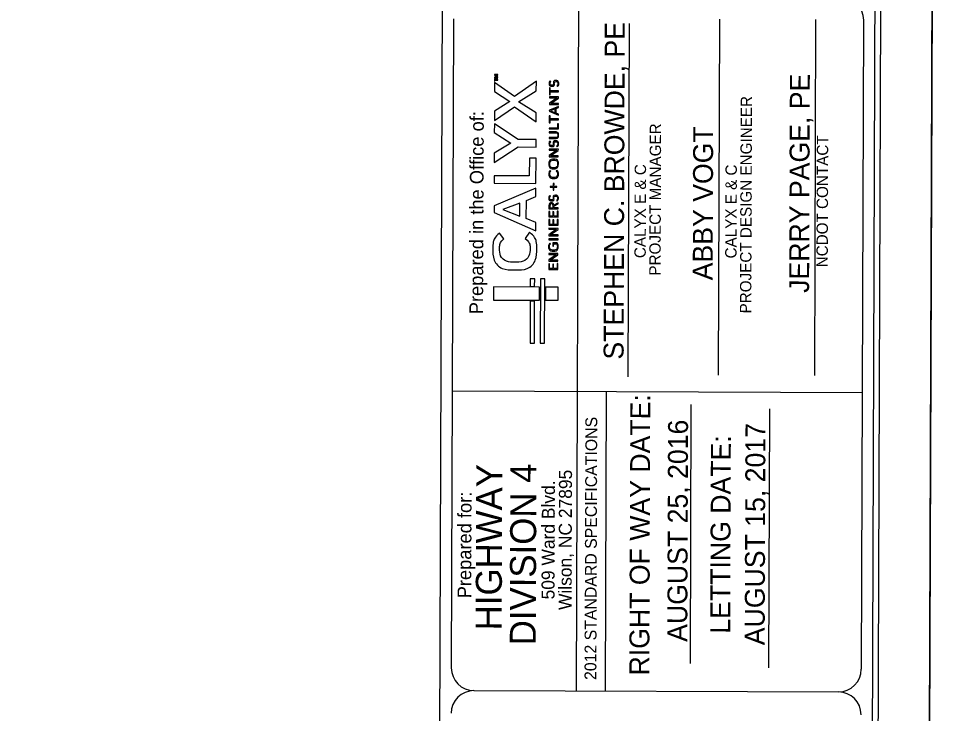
# Model space of a CAD drawing. Extents: x 2364794 to 2387902, y 795230 to 810426.
# Drawn here: x 2369718 to 2372593, y 805280 to 807415 of the extents above; entities that cross this region are included whole.
import ezdxf

# ---------------------------------------------------------------- set-up
doc = ezdxf.new("R2010")
doc.units = 0
for name, color, linetype in [('Mis Object Lines', 7, 'Continuous'), ('Old_Level_21', 7, 'Continuous'), ('Old_Level_22', 7, 'Continuous'), ('Old_Level_3', 7, 'Continuous'), ('Plan Sheet CELL', 7, 'Continuous'), ('Sub End Bent Cap Lines CELL', 7, 'Continuous')]:
    doc.layers.add(name, color=color, linetype=linetype)

msp = doc.modelspace()

# ---------------------------------------------------------------- linework, layer by layer
at = {"layer": 'Mis Object Lines'}
for p, q in [((2370994.2, 800240.4), (2371029.3, 810180.3)), ((2371438.1, 807483.9), (2371430.5, 805348.9)), ((2371047.5, 805420.2), (2371054.5, 807415.2)), ((2371868.8, 806319.9), (2371872.7, 807413.6)), ((2372164, 806318.8), (2372167.9, 807412.6)), ((2371590.5, 806314.9), (2371594.4, 807401)), ((2371050.5, 806271.1), (2372310.5, 806266.6)), ((2371523, 806269.4), (2371519.7, 805348.6)), ((2371783.8, 806229), (2371781, 805432.8)), ((2372024.6, 806215.7), (2372021.7, 805419.5)), ((2371522, 806004.1), (2371522, 806004.1)), ((2371782.5, 805830.7), (2371782.5, 805830.7)), ((2371117.2, 805350), (2372237.2, 805346))]:
    msp.add_line(p, q, dxfattribs=at)
for points in [[(2372322.9, 799850.7), (2372359.5, 810210.6)], [(2372307.4, 805415.8), (2372314.6, 807410.8)]]:
    msp.add_lwpolyline(points, dxfattribs=at)
for centre, start, end in [((2372244.6, 807411), 359.7976, 89.7976), ((2371117.1, 805420), 179.7976, 269.7976), ((2372237.1, 805416.1), 269.7976, 359.7976), ((2371116.6, 805280), 89.7976, 179.7976), ((2372236.6, 805276.1), 359.7976, 89.7976)]:
    msp.add_arc(centre, 70, start, end, dxfattribs=at)
at = {"layer": 'Old_Level_21'}
for points in [[(2364835.2, 810426.2), (2364793.5, 798638.3), (2372493.4, 798611.1), (2372535.1, 810399)], [(2380193.4, 798583.9), (2380235, 810371.8), (2372535.1, 810399), (2372493.4, 798611.1)]]:
    msp.add_lwpolyline(points, close=True, dxfattribs=at)
at = {"layer": 'Old_Level_22'}
msp.add_lwpolyline([(2372336.7, 798702.6), (2372377.9, 810368.1), (2364992.2, 810394.2), (2364951, 798728.7)], close=True, dxfattribs=at)
at = {"layer": 'Old_Level_3'}
for p, q in [((2371179.9, 807244.1), (2371179.9, 807241.9)), ((2371189.9, 807244), (2371179.9, 807244.1)), ((2371179.9, 807241.9), (2371187.5, 807238.8)), ((2371187.5, 807238.8), (2371179.9, 807235.7)), ((2371181.5, 807242.6), (2371181.5, 807242.6)), ((2371189.8, 807239.2), (2371181.5, 807242.6)), ((2371181.5, 807242.6), (2371189.9, 807242.6)), ((2371181.5, 807234.9), (2371189.8, 807238.3)), ((2371189.8, 807238.3), (2371189.8, 807239.2)), ((2371189.9, 807244), (2371189.9, 807244)), ((2371189.9, 807242.6), (2371189.9, 807244)), ((2371179.9, 807231.4), (2371179.8, 807223.4)), ((2371179.8, 807223.4), (2371181.1, 807223.4)), ((2371179.9, 807235.7), (2371179.9, 807233.4)), ((2371179.9, 807233.4), (2371189.8, 807233.4)), ((2371181.2, 807231.4), (2371179.9, 807231.4)), ((2371181.1, 807223.4), (2371181.2, 807226.7)), ((2371181.2, 807231.4), (2371181.2, 807231.4)), ((2371181.2, 807228.1), (2371181.2, 807231.4)), ((2371189.8, 807228.1), (2371181.2, 807228.1)), ((2371181.2, 807226.7), (2371189.8, 807226.7)), ((2371181.5, 807234.9), (2371181.5, 807234.9)), ((2371189.8, 807234.8), (2371181.5, 807234.9)), ((2371189.8, 807233.4), (2371189.8, 807234.8)), ((2371189.8, 807226.7), (2371189.8, 807228.1)), ((2371353.4, 807222.2), (2371351.5, 807224.7)), ((2371371.4, 807209.6), (2371373.3, 807207)), ((2371352.7, 807036.8), (2371350.8, 807039.3)), ((2371370.8, 807024.3), (2371372.6, 807021.7)), ((2371353.4, 806946.2), (2371351.5, 806948.7)), ((2371371.4, 806949.3), (2371369.7, 806947)), ((2371352.2, 806869.7), (2371350.2, 806872.2)), ((2371370.2, 806857.1), (2371372, 806854.5)), ((2371208.3, 806738.3), (2371195.3, 806756.1)), ((2371287.2, 806758.7), (2371273.7, 806739.9)), ((2371352.2, 806723.5), (2371350.1, 806725.6))]:
    msp.add_line(p, q, dxfattribs=at)
for points in [[(2371308.1, 807098.6), (2371308.2, 807126.2), (2371253.9, 807160.2), (2371308.4, 807194), (2371308.5, 807223.1), (2371241.1, 807176.6), (2371179.8, 807219), (2371179.7, 807191.2), (2371227.2, 807161), (2371179.5, 807130.8), (2371179.4, 807101.9), (2371241, 807144.6), (2371308.1, 807098.6)], [(2371351.3, 807193.3), (2371351.3, 807202.7), (2371348.7, 807202.7), (2371348.6, 807181.1), (2371351.2, 807181.1), (2371351.3, 807190.5), (2371376.7, 807190.4), (2371376.7, 807193.2), (2371351.3, 807193.3)], [(2371348.5, 807155.3), (2371348.5, 807151.7), (2371376.5, 807151.6), (2371376.6, 807154.5), (2371352.6, 807154.6), (2371376.6, 807171.2), (2371376.6, 807174.8), (2371348.6, 807174.9), (2371348.6, 807172.1), (2371372.3, 807171.9), (2371348.5, 807155.3)], [(2371369.1, 807125.2), (2371369.1, 807139.6), (2371376.5, 807142.6), (2371376.5, 807145.9), (2371348.5, 807133.9), (2371348.4, 807131.1), (2371376.4, 807118.8), (2371376.4, 807122.1), (2371369.1, 807125.2)], [(2371366.5, 807126.3), (2371366.5, 807138.5), (2371351.8, 807132.5), (2371366.5, 807126.3)], [(2371307.8, 807020.8), (2371307.9, 807043.7), (2371252.8, 807043.9), (2371179.4, 807092.5), (2371179.3, 807065.2), (2371230.4, 807033), (2371179, 807001.6), (2371178.9, 806972.9), (2371252.7, 807021), (2371307.8, 807020.8)], [(2371351, 807107.1), (2371351, 807116.5), (2371348.4, 807116.5), (2371348.3, 807094.9), (2371350.9, 807094.9), (2371351, 807104.2), (2371376.4, 807104.2), (2371376.4, 807107), (2371351, 807107.1)], [(2371348.3, 807079.3), (2371348.3, 807076.5), (2371376.3, 807076.4), (2371376.3, 807092.3), (2371373.7, 807092.3), (2371373.7, 807079.2), (2371348.3, 807079.3)], [(2371365.8, 807067.4), (2371348.2, 807067.5), (2371348.2, 807064.6), (2371365.5, 807064.6)], [(2371365.4, 807049.8), (2371348.2, 807049.8), (2371348.2, 807047), (2371365.7, 807046.9)], [(2371348, 806994.5), (2371348, 806990.9), (2371376, 806990.8), (2371376, 806993.7), (2371352, 806993.8), (2371376, 807010.5), (2371376.1, 807014), (2371348, 807014.1), (2371348, 807011.3), (2371371.8, 807011.1), (2371348, 806994.5)], [(2371307.4, 806909), (2371307.7, 806986.6), (2371287, 806986.7), (2371286.8, 806932), (2371178.8, 806932.3), (2371178.7, 806909.4), (2371307.4, 806909)], [(2371306.9, 806763.4), (2371307, 806789), (2371277.6, 806800.8), (2371277.8, 806856.6), (2371307.3, 806868.4), (2371307.4, 806894.6), (2371178.5, 806839.6), (2371178.4, 806819.8), (2371306.9, 806763.4)], [(2371351.5, 806899.8), (2371351.5, 806897.4), (2371360.4, 806897.4), (2371360.3, 806888.5), (2371362.7, 806888.4), (2371362.7, 806897.3), (2371371.6, 806897.3), (2371371.6, 806899.7), (2371362.7, 806899.7), (2371362.8, 806908.6), (2371360.4, 806908.6), (2371360.4, 806899.7), (2371351.5, 806899.8)], [(2371258.1, 806848.6), (2371205.7, 806829), (2371258, 806808.6), (2371258.1, 806848.6)], [(2371347.4, 806839.7), (2371347.4, 806831.1), (2371375.4, 806831), (2371375.4, 806833.9), (2371362.4, 806833.9), (2371362.4, 806838.6), (2371375.5, 806846.3), (2371375.5, 806849.8), (2371362.2, 806841.7)], [(2371350, 806839), (2371350, 806833.9), (2371359.8, 806833.9), (2371359.8, 806839)], [(2371362.1, 806808.6), (2371362.1, 806822.1), (2371359.5, 806822.2), (2371359.5, 806808.6), (2371349.9, 806808.6), (2371350, 806823.1), (2371347.4, 806823.1), (2371347.3, 806805.8), (2371375.3, 806805.7), (2371375.4, 806823.5), (2371372.8, 806823.5), (2371372.7, 806808.5), (2371362.1, 806808.6)], [(2371362, 806783.2), (2371362, 806796.8), (2371359.4, 806796.8), (2371359.4, 806783.2), (2371349.8, 806783.3), (2371349.9, 806797.8), (2371347.3, 806797.8), (2371347.2, 806780.4), (2371375.2, 806780.3), (2371375.3, 806798.2), (2371372.7, 806798.2), (2371372.6, 806783.2), (2371362, 806783.2)], [(2371347.1, 806751.3), (2371347.1, 806747.8), (2371375.1, 806747.7), (2371375.1, 806750.5), (2371351.1, 806750.7), (2371375.2, 806767.3), (2371375.2, 806770.9), (2371347.2, 806771), (2371347.2, 806768.1), (2371370.9, 806768), (2371347.1, 806751.3)], [(2371347.1, 806738.3), (2371347.1, 806735.5), (2371375.1, 806735.4), (2371375.1, 806738.2), (2371347.1, 806738.3)], [(2371372.9, 806726), (2371359.2, 806726.1), (2371359.1, 806716.5), (2371361.7, 806716.5), (2371361.8, 806723.2), (2371371.2, 806723.2)], [(2371346.8, 806673.7), (2371346.8, 806670.2), (2371374.8, 806670.1), (2371374.9, 806672.9), (2371350.9, 806673.1), (2371374.9, 806689.7), (2371374.9, 806693.3), (2371346.9, 806693.4), (2371346.9, 806690.5), (2371370.6, 806690.3), (2371346.8, 806673.7)], [(2371361.5, 806647.6), (2371361.6, 806661.2), (2371358.9, 806661.2), (2371358.9, 806647.6), (2371349.4, 806647.7), (2371349.4, 806662.2), (2371346.8, 806662.2), (2371346.7, 806644.8), (2371374.8, 806644.7), (2371374.8, 806662.6), (2371372.2, 806662.6), (2371372.2, 806647.6), (2371361.5, 806647.6)], [(2371303.4, 806615.3), (2371290, 806615.4), (2371289.9, 806592.7), (2371303.3, 806592.6), (2371303.4, 806615.3)], [(2371333.6, 806418.2), (2371334.3, 806615.2), (2371320.8, 806615.3), (2371320.1, 806418.3), (2371333.6, 806418.2)], [(2371318.1, 806590.1), (2371176.5, 806590.6), (2371176.4, 806550.3), (2371318, 806549.8), (2371318.1, 806590.1), (2371318.1, 806590.1)], [(2371318.1, 806590.1), (2371176.5, 806590.6), (2371176.4, 806550.3), (2371318, 806549.8), (2371318.1, 806590.1)], [(2371375.9, 806549.6), (2371376, 806589.9), (2371336.8, 806590), (2371336.6, 806549.7), (2371375.9, 806549.6)], [(2371289.3, 806418.4), (2371302.7, 806418.3), (2371303.2, 806546.8), (2371289.7, 806546.8), (2371289.3, 806418.4)]]:
    msp.add_lwpolyline(points, dxfattribs=at)
for points in [[(2371351.5, 807224.7), (2371348.9, 807222.5), (2371348.1, 807219.9), (2371348, 807216.8), (2371348, 807212.2), (2371350.5, 807207.7), (2371356, 807207.7), (2371366.2, 807207.7), (2371361.9, 807222), (2371369.8, 807222), (2371373.1, 807222), (2371374.9, 807218.8), (2371374.9, 807216), (2371374.9, 807213), (2371373.5, 807210.8), (2371371.4, 807209.6)], [(2371373.3, 807207), (2371376.2, 807209.2), (2371377.5, 807212.4), (2371377.5, 807215.8), (2371377.5, 807220.3), (2371374.5, 807225.1), (2371369.4, 807225.1), (2371359.3, 807225.1), (2371363.3, 807210.8), (2371355.7, 807210.8), (2371352.2, 807210.8), (2371350.6, 807213.8), (2371350.7, 807216.8), (2371350.7, 807219.1), (2371351.6, 807221), (2371353.4, 807222.2)], [(2371365.5, 807064.6), (2371373.5, 807064.5), (2371374.3, 807059.3), (2371374.3, 807057.1), (2371374.3, 807055), (2371373.5, 807049.7), (2371365.4, 807049.8)], [(2371365.7, 807046.9), (2371370.4, 807046.9), (2371376.9, 807048.7), (2371376.9, 807057.1), (2371377, 807065.5), (2371370.5, 807067.4), (2371365.8, 807067.4)], [(2371350.8, 807039.3), (2371348.3, 807037.1), (2371347.4, 807034.6), (2371347.4, 807031.4), (2371347.4, 807026.9), (2371349.9, 807022.4), (2371355.3, 807022.3), (2371365.6, 807022.3), (2371361.2, 807036.7), (2371369.1, 807036.6), (2371372.4, 807036.6), (2371374.2, 807033.4), (2371374.2, 807030.6), (2371374.2, 807027.7), (2371372.9, 807025.4), (2371370.8, 807024.3)], [(2371372.6, 807021.7), (2371375.6, 807023.8), (2371376.8, 807027.1), (2371376.8, 807030.5), (2371376.8, 807034.9), (2371373.9, 807039.7), (2371368.7, 807039.7), (2371358.7, 807039.8), (2371362.6, 807025.4), (2371355, 807025.4), (2371351.5, 807025.4), (2371350, 807028.5), (2371350, 807031.4), (2371350, 807033.8), (2371350.9, 807035.6), (2371352.7, 807036.8)], [(2371376.6, 806968.7), (2371376.6, 806960.3), (2371370.3, 806954.1), (2371361.8, 806954.1), (2371353.3, 806954.1), (2371347.1, 806960.4), (2371347.2, 806968.8), (2371347.2, 806977.1), (2371353.4, 806983.3), (2371361.9, 806983.3), (2371370.4, 806983.3), (2371376.6, 806977), (2371376.6, 806968.7), (2371376.6, 806968.7), (2371376.6, 806968.7), (2371376.6, 806968.7)], [(2371349.8, 806968.8), (2371349.7, 806961.6), (2371355.4, 806957.2), (2371361.8, 806957.2), (2371368.3, 806957.2), (2371374, 806961.5), (2371374, 806968.7), (2371374, 806975.9), (2371368.4, 806980.2), (2371361.9, 806980.2), (2371355.5, 806980.3), (2371349.8, 806976), (2371349.8, 806968.8), (2371349.8, 806968.8), (2371349.8, 806968.8), (2371349.8, 806968.8)], [(2371351.5, 806948.7), (2371348.4, 806946.3), (2371347.1, 806942.5), (2371347.1, 806939), (2371347, 806930.7), (2371353.2, 806924.4), (2371361.7, 806924.4), (2371370.2, 806924.4), (2371376.5, 806930.6), (2371376.5, 806938.9), (2371376.5, 806943.6), (2371374.3, 806947.5), (2371371.4, 806949.3)], [(2371369.7, 806947), (2371373, 806944.9), (2371373.9, 806941.9), (2371373.9, 806938.9), (2371373.9, 806931.7), (2371368.2, 806927.4), (2371361.7, 806927.5), (2371355.3, 806927.5), (2371349.6, 806931.8), (2371349.7, 806939), (2371349.7, 806942), (2371351.6, 806945.1), (2371353.4, 806946.2)], [(2371350.2, 806872.2), (2371347.7, 806870), (2371346.8, 806867.4), (2371346.8, 806864.3), (2371346.8, 806859.7), (2371349.3, 806855.2), (2371354.7, 806855.2), (2371365, 806855.1), (2371360.6, 806869.5), (2371368.5, 806869.5), (2371371.8, 806869.5), (2371373.6, 806866.3), (2371373.6, 806863.5), (2371373.6, 806860.5), (2371372.3, 806858.3), (2371370.2, 806857.1)], [(2371372, 806854.5), (2371375, 806856.7), (2371376.2, 806859.9), (2371376.2, 806863.3), (2371376.3, 806867.8), (2371373.3, 806872.6), (2371368.2, 806872.6), (2371358.1, 806872.6), (2371362, 806858.2), (2371354.5, 806858.3), (2371350.9, 806858.3), (2371349.4, 806861.3), (2371349.4, 806864.3), (2371349.4, 806866.6), (2371350.3, 806868.5), (2371352.2, 806869.7)], [(2371362.2, 806841.7), (2371361.8, 806846.3), (2371358.8, 806848.9), (2371354.9, 806848.9), (2371349.9, 806848.9), (2371347.4, 806845.4), (2371347.4, 806839.7)], [(2371359.8, 806839), (2371359.8, 806844.1), (2371357.6, 806845.8), (2371354.9, 806845.8), (2371352.2, 806845.8), (2371350, 806844.1), (2371350, 806839)], [(2371195.3, 806756.1), (2371180.5, 806743.5), (2371174.8, 806728.6), (2371174.7, 806711.1), (2371174.6, 806671.5), (2371201.4, 806643.1), (2371242.7, 806642.9), (2371282.8, 806642.8), (2371309.8, 806671), (2371310, 806710.7), (2371310, 806729.6), (2371303.2, 806747), (2371287.2, 806758.7)], [(2371273.7, 806739.9), (2371284.6, 806731.3), (2371289.3, 806721.3), (2371289.3, 806710.9), (2371289.2, 806684.4), (2371268.7, 806666.8), (2371241.3, 806666.9), (2371215.7, 806667), (2371195.4, 806684.7), (2371195.5, 806711.2), (2371195.5, 806720.2), (2371198.3, 806728.9), (2371208.3, 806738.3)], [(2371350.1, 806725.6), (2371347.6, 806723.2), (2371346.3, 806720), (2371346.3, 806715.5), (2371346.2, 806707.2), (2371352.4, 806700.9), (2371360.9, 806700.9), (2371369.4, 806700.8), (2371375.7, 806707.1), (2371375.7, 806715.4), (2371375.7, 806718.8), (2371374.8, 806722.9), (2371372.9, 806726)], [(2371371.2, 806723.2), (2371372.3, 806721.1), (2371373.1, 806718.3), (2371373.1, 806715.4), (2371373.1, 806708.2), (2371367.4, 806703.9), (2371361, 806704), (2371354.5, 806704), (2371348.9, 806708.3), (2371348.9, 806715.5), (2371348.9, 806719), (2371350.1, 806721.6), (2371352.2, 806723.5)]]:
    msp.add_open_spline(points, degree=3, dxfattribs=at)
at = {"layer": 'Plan Sheet CELL'}
for p, q in [((2372493.4, 798611.1), (2372535.1, 810399)), ((2372535.1, 810399), (2372493.4, 798611.1))]:
    msp.add_line(p, q, dxfattribs=at)

# ---------------------------------------------------------------- texts
at = {"layer": 'Mis Object Lines'}
for s, height, p in [('PROJECT DESIGN ENGINEER', 34.996, (2371969.1, 806509.3)), ('Prepared in the Office of:', 41.996, (2371144.8, 806506.8)), ('PROJECT MANAGER', 34.996, (2371690.4, 806625.5)), ('NCDOT CONTACT', 34.996, (2372204.2, 806651)), ('CALYX E & C', 34.996, (2371644.7, 806679.3)), ('CALYX E & C', 34.996, (2371923.8, 806678.3)), ('RIGHT OF WAY DATE: ', 61.249, (2371655.6, 805396.5)), ('2012 STANDARD SPECIFICATIONS', 36.4, (2371492.9, 805382.6)), ('LETTING DATE:', 61.249, (2371904.2, 805524.9)), ('Prepared for:', 41.996, (2371108.3, 805633.6))]:
    msp.add_text(s, height=height, rotation=89.7976, dxfattribs=at).set_placement(p)
at = {"layer": 'Sub End Bent Cap Lines CELL'}
for s, height, p in [('STEPHEN C. BROWDE, PE', 61.251, (2371576.6, 806367.4)), ('JERRY PAGE, PE', 61.251, (2372146.7, 806572.5)), ('ABBY VOGT', 61.25, (2371850.3, 806611.1)), ('AUGUST 25, 2016', 61.251, (2371772.3, 805499.8)), ('AUGUST 15, 2017', 61.251, (2372010.2, 805489.4)), ('HIGHWAY ', 80, (2371202, 805535.1)), ('DIVISION 4', 80, (2371306.8, 805489.1)), ('Wilson, NC 27895', 40, (2371416.7, 805597.7)), ('509 Ward Blvd.', 40, (2371364.4, 805630.2))]:
    msp.add_text(s, height=height, rotation=89.7976, dxfattribs=at).set_placement(p)

doc.saveas('drawing.dxf')
